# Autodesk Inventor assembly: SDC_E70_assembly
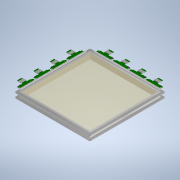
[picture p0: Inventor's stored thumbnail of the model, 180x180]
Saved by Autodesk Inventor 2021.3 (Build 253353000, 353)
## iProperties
Created: 2021-12
Part Number: SDC_E70_assembly
Document SubType Name: Assembly
Designer: kengo
Author: kengo
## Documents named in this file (5)
- C:\Users\kengo\Downloads\aida_kl_frame\AIDA_KL_frame\SDC_E70_assembly.iam
- C:\Users\kengo\Downloads\aida_kl_frame\AIDA_KL_frame\KL_chamber.ipt
- C:\Users\kengo\Downloads\aida_kl_frame\AIDA_KL_frame\ASDaeembly.iam
- C:\Users\kengo\Downloads\aida_kl_frame\AIDA_KL_frame\KL_chamber_myler.ipt
- C:\Users\kengo\Downloads\aida_kl_frame\AIDA_KL_frame\ASDassembly_mirror.ipt
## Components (6 placed, 4 different names)
1. KL_chamber:1 — メイト:2, 挿入:2, 挿入:3, メイト:4, メイト:5, 挿入:6, メイト:6, メイト:7, メイト:8, メイト:9, 挿入:7, メイト:10, 挿入:8, 挿入:9
2. ASDaeembly:2 [sub-assembly] — メイト:2, 挿入:2, 挿入:3
3. ASDaeembly:4 [sub-assembly] — メイト:4, メイト:5, 挿入:6
4. KL_chamber_myler:1 — メイト:6, メイト:7, メイト:8
5. ASDassembly_mirror:1 — メイト:9, 挿入:7
6. ASDassembly_mirror:2 — メイト:10, 挿入:8, 挿入:9
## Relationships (14: Mate 8, Insert 6)
- メイト:2 [Mate]: KL_chamber:1 ↔ ASDaeembly:2
- 挿入:2 [Insert]: KL_chamber:1 ↔ ASDaeembly:2
- 挿入:3 [Insert]: KL_chamber:1 ↔ ASDaeembly:2
- メイト:4 [Mate]: KL_chamber:1 ↔ ASDaeembly:4
- メイト:5 [Mate]: KL_chamber:1 ↔ ASDaeembly:4
- 挿入:6 [Insert]: KL_chamber:1 ↔ ASDaeembly:4
- メイト:6 [Mate]: KL_chamber:1 ↔ KL_chamber_myler:1
- メイト:7 [Mate]: KL_chamber:1 ↔ KL_chamber_myler:1
- メイト:8 [Mate]: KL_chamber:1 ↔ KL_chamber_myler:1
- メイト:9 [Mate]: KL_chamber:1 ↔ ASDassembly_mirror:1
- 挿入:7 [Insert]: KL_chamber:1 ↔ ASDassembly_mirror:1
- メイト:10 [Mate]: KL_chamber:1 ↔ ASDassembly_mirror:2
- 挿入:8 [Insert]: KL_chamber:1 ↔ ASDassembly_mirror:2
- 挿入:9 [Insert]: KL_chamber:1 ↔ ASDassembly_mirror:2
